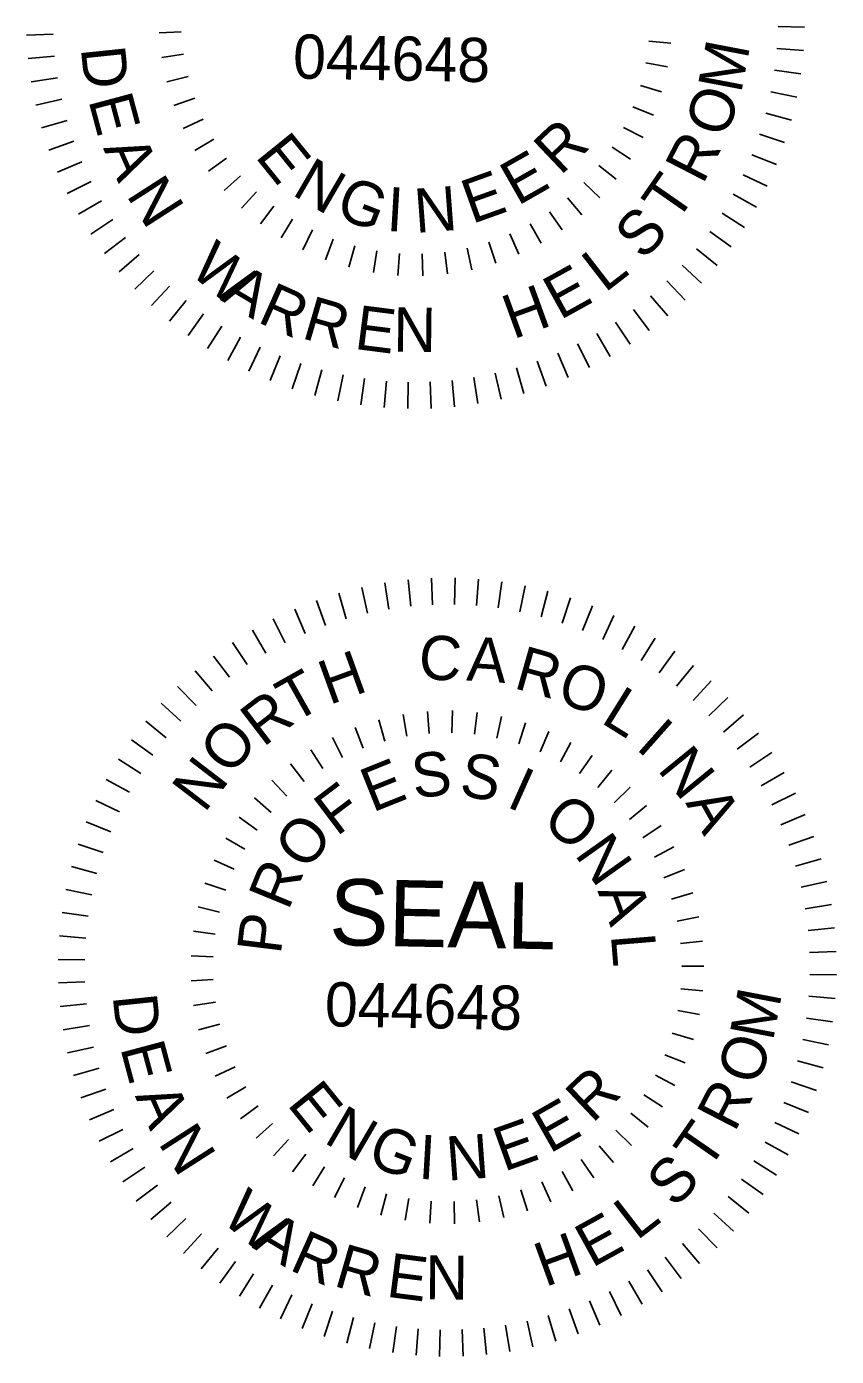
# Model space of a CAD drawing. Extents: x 0 to 2694, y -754 to 1499.
# Drawn here: x 3.6854 to 3.812, y 1.3954 to 1.6033 of the extents above; entities that cross this region are included whole.
import ezdxf

# ---------------------------------------------------------------- set-up
doc = ezdxf.new("R2010")
doc.units = 0
doc.layers.add('UBO Plan Sheet 34 CELL', color=7, linetype='Continuous')

msp = doc.modelspace()

# ---------------------------------------------------------------- linework, layer by layer
at = {"layer": 'UBO Plan Sheet 34 CELL'}
for p, q in [((3.80703, 1.60321), (3.80288, 1.60329)), ((3.68536, 1.60194), (3.6895, 1.60211)), ((3.70611, 1.6023), (3.70956, 1.60248)), ((3.78612, 1.60072), (3.78268, 1.60103)), ((3.70651, 1.59845), (3.70992, 1.59896)), ((3.80685, 1.59953), (3.80271, 1.59986)), ((3.68562, 1.59828), (3.68974, 1.59869)), ((3.7822, 1.59765), (3.7856, 1.59701)), ((3.6861, 1.59463), (3.69019, 1.5953)), ((3.70727, 1.59464), (3.71062, 1.59548)), ((3.80644, 1.59588), (3.80234, 1.59646)), ((3.78467, 1.59311), (3.78135, 1.59408)), ((3.80582, 1.59226), (3.80175, 1.59309)), ((3.6868, 1.59103), (3.69085, 1.59193)), ((3.70839, 1.59093), (3.71165, 1.59209)), ((3.7834, 1.58945), (3.78019, 1.59073)), ((3.68771, 1.58746), (3.69171, 1.58861)), ((3.70987, 1.58735), (3.713, 1.58883)), ((3.80498, 1.58868), (3.80097, 1.58975)), ((3.78177, 1.58593), (3.77871, 1.58752)), ((3.80392, 1.58515), (3.79998, 1.58647)), ((3.68884, 1.58396), (3.69276, 1.58536)), ((3.71168, 1.58393), (3.71466, 1.58569)), ((3.77983, 1.58258), (3.77693, 1.58446)), ((3.71382, 1.58069), (3.71661, 1.58274)), ((3.80265, 1.58171), (3.7988, 1.58326)), ((3.69019, 1.58054), (3.694, 1.58216)), ((3.77756, 1.57943), (3.77486, 1.58158)), ((3.69173, 1.5772), (3.69544, 1.57906)), ((3.71627, 1.57768), (3.71884, 1.57998)), ((3.775, 1.57652), (3.77252, 1.57892)), ((3.80117, 1.57834), (3.79742, 1.58011)), ((3.69347, 1.57396), (3.69706, 1.57604)), ((3.71898, 1.57492), (3.72133, 1.57746)), ((3.77218, 1.57387), (3.76994, 1.5765)), ((3.7995, 1.57507), (3.79586, 1.57707)), ((3.72196, 1.57244), (3.72404, 1.57519)), ((3.76911, 1.5715), (3.76713, 1.57434)), ((3.79763, 1.5719), (3.79413, 1.57412)), ((3.69541, 1.57084), (3.69887, 1.57312)), ((3.72515, 1.57025), (3.72697, 1.57319)), ((3.76583, 1.56944), (3.76413, 1.57246)), ((3.69753, 1.56784), (3.70084, 1.57033)), ((3.72856, 1.56838), (3.73007, 1.57149)), ((3.73212, 1.56684), (3.73333, 1.57008)), ((3.76235, 1.56771), (3.76096, 1.57087)), ((3.79557, 1.56885), (3.79221, 1.57128)), ((3.73668, 1.56901), (3.73578, 1.56566)), ((3.7396, 1.56484), (3.74016, 1.56825)), ((3.74344, 1.56439), (3.74368, 1.56784)), ((3.74732, 1.56431), (3.74722, 1.56777)), ((3.75118, 1.56461), (3.75075, 1.56804)), ((3.755, 1.56528), (3.75424, 1.56866)), ((3.75873, 1.56631), (3.75765, 1.5696)), ((3.79334, 1.56594), (3.79012, 1.56856)), ((3.69983, 1.56496), (3.70298, 1.56765)), ((3.79092, 1.56316), (3.78788, 1.56597)), ((3.70229, 1.56224), (3.70528, 1.56511)), ((3.78835, 1.56053), (3.78548, 1.56352)), ((3.70492, 1.55966), (3.70773, 1.56271)), ((3.7077, 1.55725), (3.71032, 1.56047)), ((3.78563, 1.55807), (3.78294, 1.56122)), ((3.71061, 1.55502), (3.71304, 1.55838)), ((3.78275, 1.55577), (3.78026, 1.55908)), ((3.71366, 1.55296), (3.71588, 1.55646)), ((3.77663, 1.55171), (3.77455, 1.5553)), ((3.77975, 1.55365), (3.77747, 1.5571)), ((3.71683, 1.55109), (3.71883, 1.55473)), ((3.7201, 1.54942), (3.72188, 1.55317)), ((3.77339, 1.54997), (3.77153, 1.55368)), ((3.72347, 1.54794), (3.72502, 1.55179)), ((3.77005, 1.54843), (3.76843, 1.55224)), ((3.72692, 1.54667), (3.72823, 1.55061)), ((3.73044, 1.54561), (3.73151, 1.54962)), ((3.75957, 1.54504), (3.75866, 1.54908)), ((3.76313, 1.54595), (3.76198, 1.54994)), ((3.76663, 1.54708), (3.76523, 1.55099)), ((3.73402, 1.54477), (3.73485, 1.54884)), ((3.73764, 1.54415), (3.73822, 1.54825)), ((3.7413, 1.54374), (3.74163, 1.54788)), ((3.74497, 1.54356), (3.74505, 1.54771)), ((3.74865, 1.5436), (3.74848, 1.54774)), ((3.75231, 1.54386), (3.7519, 1.54798)), ((3.75596, 1.54434), (3.75529, 1.54843)), ((3.74138, 1.51631), (3.74204, 1.51222)), ((3.74502, 1.51679), (3.74544, 1.51266)), ((3.74869, 1.51705), (3.74885, 1.5129)), ((3.75237, 1.51709), (3.75228, 1.51294)), ((3.75604, 1.5169), (3.75571, 1.51277)), ((3.75969, 1.5165), (3.75912, 1.51239)), ((3.76332, 1.51588), (3.76249, 1.51181)), ((3.7342, 1.51469), (3.73536, 1.5107)), ((3.73777, 1.51561), (3.73868, 1.51156)), ((3.76689, 1.51503), (3.76583, 1.51102)), ((3.77042, 1.51398), (3.76911, 1.51003)), ((3.72729, 1.51222), (3.72891, 1.5084)), ((3.73071, 1.51356), (3.73211, 1.50965)), ((3.77387, 1.51271), (3.77232, 1.50886)), ((3.72395, 1.51068), (3.7258, 1.50696)), ((3.77723, 1.51123), (3.77546, 1.50748)), ((3.78051, 1.50956), (3.77851, 1.50592)), ((3.72071, 1.50893), (3.72279, 1.50534)), ((3.78368, 1.50769), (3.78146, 1.50418)), ((3.71758, 1.507), (3.71987, 1.50354)), ((3.78672, 1.50563), (3.7843, 1.50226)), ((3.71458, 1.50488), (3.71707, 1.50157)), ((3.78964, 1.50339), (3.78702, 1.50018)), ((3.71171, 1.50258), (3.7144, 1.49942)), ((3.70898, 1.50011), (3.71186, 1.49712)), ((3.79242, 1.50098), (3.78961, 1.49793)), ((3.70641, 1.49749), (3.70946, 1.49468)), ((3.79504, 1.49841), (3.79205, 1.49554)), ((3.74424, 1.49575), (3.74483, 1.49234)), ((3.74808, 1.49623), (3.74834, 1.49278)), ((3.75196, 1.49634), (3.75189, 1.49289)), ((3.75189, 1.49289), (3.75196, 1.49634)), ((3.75583, 1.49607), (3.75542, 1.49264)), ((3.75965, 1.49544), (3.75892, 1.49206)), ((3.79751, 1.49568), (3.79435, 1.493)), ((3.704, 1.49471), (3.70721, 1.49209)), ((3.73677, 1.49368), (3.73801, 1.49045)), ((3.74046, 1.4949), (3.74138, 1.49156)), ((3.76339, 1.49444), (3.76234, 1.49114)), ((3.76702, 1.49308), (3.76566, 1.4899)), ((3.70176, 1.4918), (3.70513, 1.48937)), ((3.73323, 1.49212), (3.73477, 1.48902)), ((3.7705, 1.49138), (3.76884, 1.48835)), ((3.79981, 1.49281), (3.79649, 1.49032)), ((3.69971, 1.48875), (3.70321, 1.48653)), ((3.72984, 1.49022), (3.73168, 1.48728)), ((3.77381, 1.48935), (3.77186, 1.48649)), ((3.80193, 1.48981), (3.79847, 1.48752)), ((3.72666, 1.488), (3.72878, 1.48526)), ((3.7769, 1.48701), (3.77468, 1.48435)), ((3.80386, 1.48669), (3.80027, 1.4846)), ((3.69783, 1.48558), (3.70147, 1.48358)), ((3.72371, 1.48549), (3.72608, 1.48296)), ((3.72102, 1.4827), (3.72361, 1.48042)), ((3.77974, 1.48438), (3.77728, 1.48195)), ((3.80561, 1.48344), (3.80189, 1.48159)), ((3.69617, 1.4823), (3.69991, 1.48053)), ((3.78233, 1.48149), (3.77964, 1.47931)), ((3.69468, 1.47894), (3.69854, 1.47739)), ((3.7186, 1.47967), (3.72141, 1.47765)), ((3.78462, 1.47836), (3.78174, 1.47645)), ((3.80715, 1.48011), (3.80333, 1.47848)), ((3.7165, 1.47642), (3.71948, 1.47467)), ((3.80849, 1.47668), (3.80458, 1.47529)), ((3.69342, 1.47549), (3.69736, 1.47418)), ((3.7866, 1.47503), (3.78355, 1.47341)), ((3.71471, 1.47298), (3.71785, 1.47154)), ((3.80962, 1.47319), (3.80563, 1.47203)), ((3.69236, 1.47196), (3.69637, 1.4709)), ((3.78825, 1.47152), (3.78505, 1.4702)), ((3.69152, 1.46839), (3.69558, 1.46756)), ((3.71326, 1.46938), (3.71653, 1.46825)), ((3.78955, 1.46787), (3.78624, 1.46687)), ((3.81054, 1.46962), (3.80649, 1.46872)), ((3.81124, 1.46601), (3.80714, 1.46535)), ((3.6909, 1.46476), (3.695, 1.46419)), ((3.71217, 1.46566), (3.71553, 1.46485)), ((3.7905, 1.46411), (3.78711, 1.46343)), ((3.71144, 1.46185), (3.71486, 1.46138)), ((3.81172, 1.46237), (3.80759, 1.46195)), ((3.69049, 1.46111), (3.69462, 1.46078)), ((3.79107, 1.46028), (3.78764, 1.45993)), ((3.71108, 1.45799), (3.71453, 1.45784)), ((3.74833, 1.45863), (3.74833, 1.45863)), ((3.81198, 1.4587), (3.80783, 1.45854)), ((3.69031, 1.45744), (3.69445, 1.45736)), ((3.79128, 1.45641), (3.78782, 1.45639)), ((3.69034, 1.45376), (3.69449, 1.45393)), ((3.7111, 1.45412), (3.71455, 1.4543)), ((3.81202, 1.45503), (3.80787, 1.45511)), ((3.79111, 1.45253), (3.78767, 1.45285)), ((3.81183, 1.45135), (3.8077, 1.45168)), ((3.69061, 1.45009), (3.69473, 1.45051)), ((3.71149, 1.45026), (3.71491, 1.45078)), ((3.78719, 1.44947), (3.79059, 1.44882)), ((3.69108, 1.44645), (3.69518, 1.44711)), ((3.71225, 1.44646), (3.7156, 1.4473)), ((3.81142, 1.4477), (3.80732, 1.44828)), ((3.78965, 1.44492), (3.78634, 1.4459)), ((3.69178, 1.44284), (3.69583, 1.44375)), ((3.71338, 1.44275), (3.71663, 1.44391)), ((3.8108, 1.44408), (3.80674, 1.4449)), ((3.78838, 1.44126), (3.78517, 1.44255)), ((3.80996, 1.4405), (3.80595, 1.44157)), ((3.6927, 1.43928), (3.69669, 1.44043)), ((3.71486, 1.43917), (3.71798, 1.44064)), ((3.78676, 1.43775), (3.7837, 1.43934)), ((3.69383, 1.43578), (3.69774, 1.43718)), ((3.71667, 1.43575), (3.71964, 1.43751)), ((3.80891, 1.43697), (3.80496, 1.43829)), ((3.78482, 1.4344), (3.78191, 1.43627)), ((3.80764, 1.43353), (3.80378, 1.43508)), ((3.69518, 1.43236), (3.69899, 1.43398)), ((3.71881, 1.43251), (3.7216, 1.43455)), ((3.78255, 1.43124), (3.77984, 1.4334)), ((3.69671, 1.42902), (3.70043, 1.43087)), ((3.72125, 1.4295), (3.72383, 1.4318)), ((3.77999, 1.42834), (3.77751, 1.43074)), ((3.80616, 1.43016), (3.80241, 1.43193)), ((3.72396, 1.42674), (3.72631, 1.42928)), ((3.80449, 1.42688), (3.80085, 1.42888)), ((3.69846, 1.42578), (3.70205, 1.42786)), ((3.72694, 1.42425), (3.72903, 1.42701)), ((3.77717, 1.42568), (3.77492, 1.42832)), ((3.70039, 1.42265), (3.70385, 1.42494)), ((3.73014, 1.42206), (3.73196, 1.42501)), ((3.77081, 1.42126), (3.76911, 1.42427)), ((3.77409, 1.42332), (3.77212, 1.42615)), ((3.80262, 1.42371), (3.79911, 1.42594)), ((3.70251, 1.41965), (3.70583, 1.42214)), ((3.73354, 1.4202), (3.73506, 1.4233)), ((3.76734, 1.41953), (3.76595, 1.42269)), ((3.80056, 1.42067), (3.79719, 1.42309)), ((3.7371, 1.41866), (3.73832, 1.4219)), ((3.74166, 1.42082), (3.74077, 1.41748)), ((3.74458, 1.41666), (3.74515, 1.42007)), ((3.75999, 1.4171), (3.75922, 1.42048)), ((3.76372, 1.41813), (3.76264, 1.42142)), ((3.79832, 1.41776), (3.79511, 1.42037)), ((3.70481, 1.41678), (3.70797, 1.41947)), ((3.74843, 1.41621), (3.74866, 1.41966)), ((3.7523, 1.41613), (3.75221, 1.41959)), ((3.75617, 1.41643), (3.75574, 1.41986)), ((3.70728, 1.41406), (3.71027, 1.41693)), ((3.79591, 1.41497), (3.79286, 1.41779)), ((3.7099, 1.41148), (3.71272, 1.41453)), ((3.79334, 1.41235), (3.79046, 1.41534)), ((3.71268, 1.40907), (3.7153, 1.41228)), ((3.79061, 1.40988), (3.78792, 1.41304)), ((3.7156, 1.40683), (3.71802, 1.4102)), ((3.78774, 1.40758), (3.78525, 1.4109)), ((3.71864, 1.40478), (3.72086, 1.40828)), ((3.78474, 1.40546), (3.78245, 1.40892)), ((3.72181, 1.40291), (3.72381, 1.40654)), ((3.77837, 1.40178), (3.77652, 1.4055)), ((3.78161, 1.40353), (3.77953, 1.40712)), ((3.72509, 1.40124), (3.72686, 1.40498)), ((3.72845, 1.39976), (3.73001, 1.40361)), ((3.77503, 1.40025), (3.77341, 1.40406)), ((3.7319, 1.39849), (3.73321, 1.40243)), ((3.73543, 1.39743), (3.73649, 1.40144)), ((3.76812, 1.39777), (3.76696, 1.40176)), ((3.77161, 1.3989), (3.77021, 1.40281)), ((3.73901, 1.39659), (3.73983, 1.40065)), ((3.74263, 1.39597), (3.74321, 1.40007)), ((3.74628, 1.39556), (3.74661, 1.3997)), ((3.74995, 1.39538), (3.75004, 1.39953)), ((3.75363, 1.39542), (3.75347, 1.39956)), ((3.7573, 1.39568), (3.75688, 1.3998)), ((3.76094, 1.39615), (3.76028, 1.40025)), ((3.76455, 1.39685), (3.76364, 1.4009))]:
    msp.add_line(p, q, dxfattribs=at)

# ---------------------------------------------------------------- texts
for s, height, rotation, p in [('044648', 0.006909, 358.8648, (3.72698, 1.59519)), ('D', 0.00691, 275.9811, (3.69383, 1.59991)), ('M', 0.00691, 79.1773, (3.7971, 1.59272)), ('E', 0.00691, 284.9836, (3.69499, 1.59181)), ('O', 0.00691, 71.1829, (3.79472, 1.58569)), ('E', 0.00691, 308.9349, (3.72098, 1.58297)), ('R', 0.00691, 43.4297, (3.76884, 1.57988)), ('R', 0.00691, 62.7337, (3.79111, 1.57847)), ('A', 0.00691, 293.8062, (3.69729, 1.58429)), ('N', 0.00691, 329.7899, (3.72667, 1.57709)), ('E', 0.00691, 29.6586, (3.76216, 1.5752)), ('E', 0.00691, 19.6727, (3.75501, 1.57239)), ('T', 0.00691, 55.228, (3.78693, 1.57238)), ('N', 0.00691, 302.6889, (3.70085, 1.57695)), ('G', 0.00691, 338.5562, (3.73337, 1.57372)), ('I', 0.00691, 356.651, (3.74155, 1.57135)), ('N', 0.00691, 4.2806, (3.74623, 1.57102)), ('S', 0.00691, 46.5552, (3.78179, 1.56658)), ('W', 0.00691, 320.3641, (3.71061, 1.56485)), ('L', 0.00691, 37.7626, (3.7758, 1.56158)), ('E', 0.00691, 28.88, (3.76879, 1.55734)), ('A', 0.00691, 329.3125, (3.71556, 1.56059)), ('R', 0.00691, 336.0279, (3.72128, 1.55716)), ('H', 0.00691, 19.9974, (3.76146, 1.55436)), ('R', 0.00691, 343.8077, (3.7282, 1.55463)), ('E', 0.00691, 352.7158, (3.73649, 1.55292)), ('N', 0.00691, 359.3001, (3.74269, 1.55249)), ('C', 0.00691, 356.2217, (3.74653, 1.50136)), ('A', 0.00691, 356.2217, (3.75407, 1.50107)), ('H', 0.00691, 19.9324, (3.73269, 1.49719)), ('R', 0.00691, 344.2124, (3.76137, 1.49991)), ('O', 0.00691, 341.1556, (3.76802, 1.49779)), ('T', 0.00691, 29.3644, (3.72707, 1.49429)), ('L', 0.00691, 328.0193, (3.77499, 1.49457)), ('R', 0.00691, 37.5253, (3.72235, 1.49052)), ('I', 0.00691, 318.4439, (3.78048, 1.49045)), ('O', 0.00691, 50.5821, (3.71725, 1.48597)), ('N', 0.00691, 309.1494, (3.78388, 1.48712)), ('N', 0.00691, 52.5415, (3.71317, 1.48021)), ('E', 0.00691, 21.8091, (3.73945, 1.48037)), ('S', 0.00691, 6.5129, (3.74598, 1.48261)), ('S', 0.00691, 351.2166, (3.75289, 1.48305)), ('I', 0.00691, 335.9204, (3.76021, 1.48141)), ('F', 0.00691, 37.1054, (3.73384, 1.47657)), ('O', 0.00691, 320.6242, (3.76572, 1.47861)), ('A', 0.00691, 299.3819, (3.78834, 1.48193)), ('O', 0.00691, 52.4016, (3.72914, 1.47109)), ('N', 0.00691, 305.3279, (3.77095, 1.47388)), ('R', 0.00691, 67.6979, (3.72628, 1.46494)), ('SEAL', 0.010372, 358.8648, (3.73264, 1.45971)), ('A', 0.00691, 290.0317, (3.77463, 1.46815)), ('P', 0.00691, 82.9941, (3.7251, 1.45811)), ('L', 0.00691, 274.7354, (3.77673, 1.46126)), ('044648', 0.006909, 358.8648, (3.73196, 1.44701)), ('D', 0.00691, 275.9811, (3.69882, 1.45173)), ('M', 0.00691, 79.1773, (3.80208, 1.44454)), ('O', 0.00691, 71.1829, (3.7997, 1.43751)), ('E', 0.00691, 284.9836, (3.69998, 1.44363)), ('R', 0.00691, 43.4297, (3.77382, 1.4317)), ('E', 0.00691, 308.9349, (3.72597, 1.43478)), ('R', 0.00691, 62.7337, (3.79609, 1.43028)), ('A', 0.00691, 293.8062, (3.70227, 1.43611)), ('E', 0.00691, 29.6586, (3.76715, 1.42701)), ('N', 0.00691, 329.7899, (3.73166, 1.42891)), ('E', 0.00691, 19.6727, (3.76, 1.42421)), ('T', 0.00691, 55.228, (3.79192, 1.4242)), ('N', 0.00691, 302.6889, (3.70583, 1.42877)), ('G', 0.00691, 338.5562, (3.73835, 1.42554)), ('I', 0.00691, 356.651, (3.74654, 1.42316)), ('N', 0.00691, 4.2806, (3.75122, 1.42284)), ('S', 0.00691, 46.5552, (3.78678, 1.4184)), ('W', 0.00691, 320.3641, (3.71559, 1.41667)), ('L', 0.00691, 37.7626, (3.78079, 1.41339)), ('A', 0.00691, 329.3125, (3.72054, 1.41241)), ('E', 0.00691, 28.88, (3.77378, 1.40916)), ('R', 0.00691, 336.0279, (3.72627, 1.40898)), ('H', 0.00691, 19.9974, (3.76645, 1.40618)), ('R', 0.00691, 343.8077, (3.73319, 1.40645)), ('E', 0.00691, 352.7158, (3.74148, 1.40473)), ('N', 0.00691, 359.3001, (3.74768, 1.4043))]:
    msp.add_text(s, height=height, rotation=rotation, dxfattribs=at).set_placement(p)

doc.saveas('drawing.dxf')
